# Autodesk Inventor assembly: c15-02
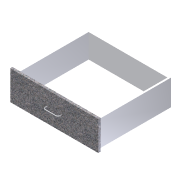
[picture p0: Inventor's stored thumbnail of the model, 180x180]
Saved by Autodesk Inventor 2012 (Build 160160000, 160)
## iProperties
Created: 2011-02
Part Number: c15-02
Document SubType Name: Assembly
Designer: Beta-8540w
Author: Beta-8540w
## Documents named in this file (13)
- C:\Users\VMuser\Desktop\Inventor 2012 Essentials\Assemblies\Chapter 15\c15-02.iam
- C:\Users\VMuser\Desktop\Inventor 2012 Essentials\Parts\Chapter 15\c15-11\c15-11-01.ipt
- C:\Inventor 2012 Essentials\Parts\Chapter 15\c15-11.ipt
- C:\Users\VMuser\Desktop\Inventor 2012 Essentials\Parts\Chapter 15\c15-12\c15-12-01.ipt
- C:\Inventor 2012 Essentials\Parts\Chapter 15\c15-12.ipt
- C:\Users\VMuser\Desktop\Inventor 2012 Essentials\Parts\Chapter 15\c15-13\c15-13-01.ipt
- C:\Inventor 2012 Essentials\Parts\Chapter 15\c15-13.ipt
- C:\Users\VMuser\Desktop\Inventor 2012 Essentials\Parts\Chapter 15\c15-14.ipt
- C:\Users\VMuser\Desktop\Inventor 2012 Essentials\Parts\Chapter 15\c15-15\c15-15-01.ipt
- C:\Inventor 2012 Essentials\Parts\Chapter 15\c15-15.ipt
- C:\Users\VMuser\Desktop\Inventor 2012 Essentials\Parts\Chapter 15\c15-16.ipt
- C:\Users\VMuser\Desktop\Inventor 2012 Essentials\Parts\Chapter 15\c15-17.ipt
- C:\Users\VMuser\Desktop\Inventor 2012 Essentials\Content Center Files\en-US\ANSI B18.6.3\ANSI B18.6.3 - 8-36 UNF - 0.875.ipt
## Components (9 placed, 8 different names)
1. c15-11-01:1 — Mate:1, Flush:1, Mate:2, Mate:6, Mate:7, Mate:10, Mate:11, Wire Pull Insert 1, Wire Pull Insert 2, Wire Pull constraint, Insert:4
2. c15-12-01:1 — Flush:2, Mate:9, Flush:4, Flush:5
3. c15-13-01:1 — Mate:1, Flush:1, Mate:2, Flush:2, Flush:3, Mate:8, Mate:9, Flush:4, Flush:5
4. c15-14:1 — Flush:3, Mate:10, Mate:11
5. c15-15-01:1 — Mate:6, Mate:7, Mate:8
6. c15-16:1 — Wire Pull Insert 1, Wire Pull Insert 2
7. c15-17:1
8. Cross Recessed Truss Head Machine Screw - Type IA - Inch No. 8 - 36 - 7/8:1 — Wire Pull constraint
9. Cross Recessed Truss Head Machine Screw - Type IA - Inch No. 8 - 36 - 7/8:2 — Insert:4
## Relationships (17: Mate 8, Flush 5, Insert 4)
- Mate:1: c15-11-01:1 ↔ c15-13-01:1
- Flush:1: c15-11-01:1 ↔ c15-13-01:1
- Mate:2: c15-11-01:1 ↔ c15-13-01:1
- Flush:2: c15-12-01:1 ↔ c15-13-01:1
- Flush:3: c15-13-01:1 ↔ c15-14:1
- Mate:6: c15-11-01:1 ↔ c15-15-01:1
- Mate:7: c15-11-01:1 ↔ c15-15-01:1
- Mate:8: c15-13-01:1 ↔ c15-15-01:1
- Mate:9: c15-12-01:1 ↔ c15-13-01:1
- Flush:4: c15-12-01:1 ↔ c15-13-01:1
- Flush:5: c15-12-01:1 ↔ c15-13-01:1
- Mate:10: c15-11-01:1 ↔ c15-14:1
- Mate:11: c15-11-01:1 ↔ c15-14:1
- Wire Pull Insert 1 [Insert]: c15-11-01:1 ↔ c15-16:1
- Wire Pull Insert 2 [Insert]: c15-11-01:1 ↔ c15-16:1
- Wire Pull constraint [Insert]: c15-11-01:1 ↔ Cross Recessed Truss Head Machine Screw - Type IA - Inch No. 8 - 36 - 7/8:1
- Insert:4: c15-11-01:1 ↔ Cross Recessed Truss Head Machine Screw - Type IA - Inch No. 8 - 36 - 7/8:2
